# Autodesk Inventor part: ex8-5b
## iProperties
Author: Administrator
Created: 2001-10
Part Number: ex8-5b
Document SubType Name: Modeling
Designer: Administrator
Control State: 0
Master: False
Checked Out: False
PropertySet Name: Design Tracking Control
Shininess: 64.0
Angle Display Precision: 2
Document Length Units: 11272
Document Angle Units: 11286
Document Time Units: 11279
Document Mass Units: 11290
Document Length Units Precision: 3
Document Angle Units Precision: 2
Compacted: False
PropertySet Name: _Private Model Information
Density: 0.0
Volumn: 0.0
Area: 0.0
PropertySet Name: Model Information
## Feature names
1. Extrusion1
